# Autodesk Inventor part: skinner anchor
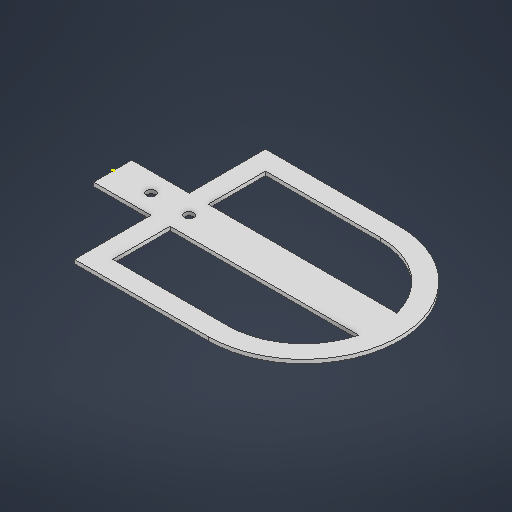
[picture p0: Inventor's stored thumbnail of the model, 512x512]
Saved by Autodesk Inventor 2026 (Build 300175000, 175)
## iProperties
Created: 2025-10
Part Number: skinner anchor
Material: Generic
Document SubType Name: Modeling
Designer: sab273
Density: 1 g/cm^3
Appearance: Default
Author: sab273
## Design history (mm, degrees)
sketch "Sketch1"
  geometry: L1 (-30, 50)-(-100, 50); L2 (-30, -50)-(-100, -50); L3 (-40, -40)-(-100, -40); L4 (-100, 40)-(-40, 40); L5 (0, 10)-(-30, 10); L6 (-40, 10)-(-138.73, 10); L7 (0, 10)-(0, -10); L8 (0, -10)-(-30, -10); L9 (-40, -10)-(-138.73, -10); L10 (0, 10)-(-30, 10); L11 (-30, 10)-(-30, 50); L12 (-30, -50)-(-30, -10); L13 (-40, 10)-(-40, 40); L14 (-40, -40)-(-40, -10); C1 r 2.4 at (-20, 0); C2 r 2.4 at (-40, 0); A1 r 50 centre (-100, 0) between (-100, 50) and (-100, -50); A2 r 40 centre (-100, 0) between (-100, 40) and (-138.73, 10); A3 r 40 centre (-100, 0) between (-138.73, -10) and (-100, -40); 1 further point
  constraints: 28 end point, 6 point on circle, 5 centre point, 2 parallel, 2 perpendicular, 2 point on line, 1 collinear, 1 horizontal, 1 tangent, 1 vertical
extrude "Extrusion1" new body sketch "Sketch1" distance "d19" = 2; taper "d20" = 0 deg
sketch "Sketch2"
  geometry: 1 further point
body "Solid1"
